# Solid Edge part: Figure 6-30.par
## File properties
Author: TIET
Template: Normal.par
Last saved by: CADCIM
Revision: 6
Application: Solid Edge
Accuracy: 0.99
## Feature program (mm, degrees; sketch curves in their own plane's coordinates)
sketch for "unnamed Protrusion 1" plane through (0, 0, 0) normal (0, 0, 1) x-axis (1, 0, 0)
  line (-52.1766, -31.6987) -> (52.1766, -31.6987)
  line (52.1766, -31.6987) -> (52.1766, 31.6987)
  line (52.1766, 31.6987) -> (-52.1766, 31.6987)
  line (-52.1766, 31.6987) -> (-52.1766, -31.6987)
extrude "unnamed Protrusion 1" add finite 57.15 along +normal
sketch for "ExtrudedCutout_1" plane through (0, 0, 57.15) normal (0, 0, 1) x-axis (0, 1, 0)
  line (-31.6987, 0) -> (8.7819, 0)
  line (8.7819, 0) -> (8.7819, -52.1766)
extrude "ExtrudedCutout_1" cut finite 41.275 along -normal
fillet "Round_7" radius 5
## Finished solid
Body 1: solid body, 18 faces, 45 edges, 29 vertices.
  Faces by surface: plane 9, spline 6, cylinder 3
  Edges by curve: line 24, curve on surface 15, circle 3, spline 3
Bounding box of the edges (mm; curved faces can reach further): 104.353 x 63.397 x 57.150, from (-52.1766, -31.6987, 0) to (52.1766, 31.6987, 57.15).
Cylindrical faces by radius (mm): R5 x3
Planar faces by outward normal: +x 2, +y 1, +z 2, -x 1, -y 2, -z 1
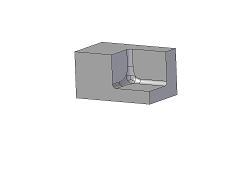
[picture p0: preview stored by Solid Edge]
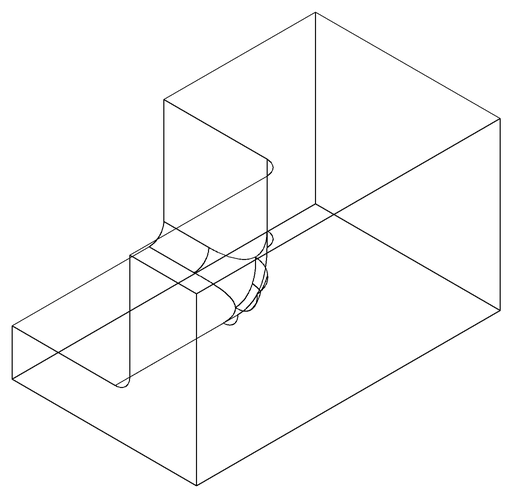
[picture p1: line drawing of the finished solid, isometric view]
